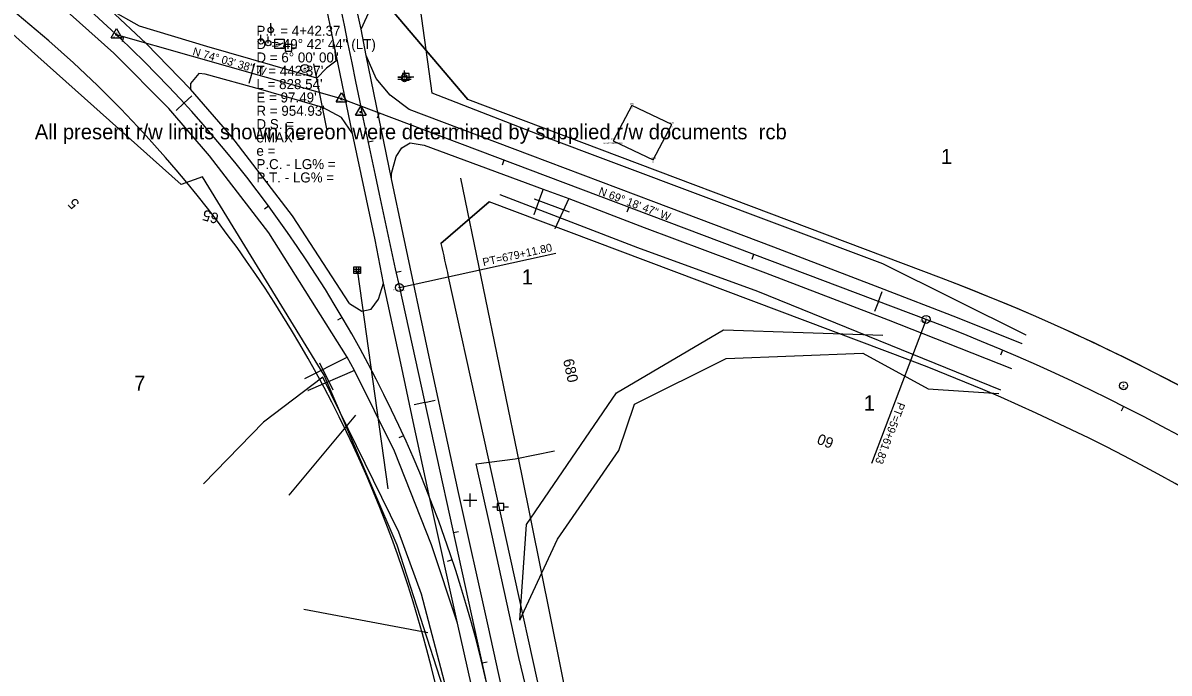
# Model space of a CAD drawing. Extents: x 2519952 to 2531965, y 848341 to 887632.
# Drawn here: x 2522518 to 2523377, y 863427 to 863914 of the extents above; entities that cross this region are included whole.
import ezdxf

# ---------------------------------------------------------------- set-up
doc = ezdxf.new("R2010")
doc.units = 0
for name, color, linetype in [('RD_EV_JW', 7, 'Continuous'), ('RD_EX_Bldg', 7, 'Continuous'), ('RD_EX_Bldg_txCode', 7, 'Continuous'), ('RD_EX_DR_Inlet', 7, 'Continuous'), ('RD_EX_DR_Pipe', 7, 'Continuous'), ('RD_EX_Driveway', 7, 'Continuous'), ('RD_EX_DV_Prop', 7, 'Continuous'), ('RD_EX_DV_TX_Prop', 7, 'Continuous'), ('RD_EX_H2O', 7, 'Continuous'), ('RD_EX_Misc', 7, 'Continuous'), ('RD_EX_Road', 7, 'Continuous'), ('RD_EX_RW', 7, 'Continuous'), ('RD_EX_RW_TX', 7, 'Continuous'), ('RD_EX_UT', 7, 'Continuous'), ('RD_EX_VEG', 7, 'Continuous'), ('RD_HC_Cl', 7, 'Continuous'), ('RD_HC_Data', 7, 'Continuous'), ('RD_HC_Data_Tic', 7, 'Continuous'), ('RD_HC_Survey_txCode', 7, 'Continuous'), ('RD_HC_TX_Sta50', 7, 'Continuous'), ('RD_HC_txCode', 7, 'Continuous'), ('RD_SMD_Locator', 7, 'Continuous')]:
    doc.layers.add(name, color=color, linetype=linetype)

msp = doc.modelspace()

# ---------------------------------------------------------------- linework, layer by layer
at = {"layer": 'RD_EV_JW'}
for points in [[(2522920.53, 863055.57), (2522899.94, 863070.57), (2522889.91, 863131.31), (2522869.96, 863279.01), (2522857.45, 863332.73), (2522834.29, 863420.16), (2522816.96, 863485.78), (2522800.18, 863532.41), (2522743.02, 863648.45), (2522698.57, 863614.71), (2522653.78, 863568.51)], [(2522920.53, 863055.57), (2522967.57, 863070.75), (2522981.27, 863100.18), (2522962.21, 863158.09), (2522937.17, 863227.1), (2522907.56, 863365.86), (2522890.04, 863438.41), (2522868, 863538.84), (2522858.07, 863583.56), (2522887.19, 863587.35), (2522916.66, 863593.29)]]:
    msp.add_lwpolyline(points, dxfattribs=at)
at = {"layer": 'RD_EX_Bldg'}
msp.add_lwpolyline([(2522960.63, 863825.67), (2522990.59, 863811.41), (2523004.65, 863837.91), (2522974.69, 863852.17), (2522960.63, 863825.67)], dxfattribs=at)
at = {"layer": 'RD_EX_DR_Inlet'}
for p, q in [((2522766.4, 863729.6), (2522771.4, 863729.6)), ((2522766.4, 863727.9), (2522771.4, 863727.9)), ((2522768.1, 863731.3), (2522768.1, 863726.3)), ((2522769.8, 863731.3), (2522769.8, 863726.3))]:
    msp.add_line(p, q, dxfattribs=at)
msp.add_lwpolyline([(2522766.4, 863726.3), (2522766.4, 863731.3), (2522771.4, 863731.3), (2522771.4, 863726.3)], close=True, dxfattribs=at)
at = {"layer": 'RD_EX_DR_Pipe'}
for p, q in [((2522746.04, 863834.81), (2522736.32, 863883.57)), ((2522901.44, 863782.38), (2522927.64, 863772.55)), ((2522769.09, 863727.62), (2522791.79, 863564.8)), ((2522740.58, 863659.27), (2522750.51, 863639.06))]:
    msp.add_line(p, q, dxfattribs=at)
at = {"layer": 'RD_EX_Driveway'}
for p, q in [((2522927.39, 863782.47), (2522917, 863759.7)), ((2522729.74, 863647.45), (2522761.34, 863663.47)), ((2522766.87, 863653.47), (2522732.02, 863638.61))]:
    msp.add_line(p, q, dxfattribs=at)
for points in [[(2522771.84, 863909.39), (2522780.26, 863928.09), (2522784.52, 863933.36), (2522789.39, 863937.12), (2522787.58, 863945.49), (2522773.78, 863941.61), (2522764.08, 863945.89)], [(2522908.2, 863789.47), (2522906.31, 863784.3), (2522901.18, 863770.21)]]:
    msp.add_lwpolyline(points, dxfattribs=at)
at = {"layer": 'RD_EX_DV_Prop'}
for p, q in [((2522795.07, 863923.37), (2522851.83, 863856.71)), ((2523206.85, 863722.65), (2522851.83, 863856.71)), ((2522831.66, 863748.88), (2522867.9, 863780.1)), ((2523183.54, 863660.91), (2522867.9, 863780.1)), ((2522837.15, 863723.81), (2522952.89, 863198.2))]:
    msp.add_line(p, q, dxfattribs=at)
for centre, radius, start, end in [((2521934.11, 863209.88), 917.43, 12.4185, 62.13074), ((2533991.57, 866180.03), 11421.66, 192.289656, 192.418432), ((2522660.36, 862275.4), 1546.99, 54.66603, 69.31315), ((2522660.36, 862275.4), 1480.99, 51.25287, 69.31316)]:
    msp.add_arc(centre, radius, start, end, dxfattribs=at)
at = {"layer": 'RD_EX_H2O'}
for p, q in [((2522767.7, 863619.95), (2522717.61, 863559.92)), ((2522821.78, 863456.92), (2522728.84, 863474.4))]:
    msp.add_line(p, q, dxfattribs=at)
for points in [[(2522890.89, 863466.28), (2522895.7, 863538.1), (2522943.3, 863607.52), (2522943.3, 863607.52), (2522963.12, 863636.85), (2523043.42, 863684.11), (2523162.85, 863679.99)], [(2522964.9, 863593.49), (2522976.59, 863628.23), (2523045.48, 863662.45), (2523147.88, 863666.63), (2523196.8, 863639.73), (2523249.79, 863636.38)], [(2522890.89, 863466.28), (2522918.88, 863526.99), (2522964.9, 863593.49)]]:
    msp.add_lwpolyline(points, dxfattribs=at)
at = {"layer": 'RD_EX_Misc'}
for p, q in [((2522853.61, 863551.25), (2522853.61, 863561.25)), ((2522848.61, 863556.25), (2522858.61, 863556.25))]:
    msp.add_line(p, q, dxfattribs=at)
at = {"layer": 'RD_EX_Road'}
for p, q in [((2522751.62, 863897.74), (2522733.8, 863986.7)), ((2522771.84, 863909.39), (2522764.08, 863945.89)), ((2522775.53, 863889.71), (2522771.84, 863909.39)), ((2522765.47, 863831.25), (2522751.62, 863897.74)), ((2522794.55, 863797.32), (2522775.53, 863889.71)), ((2522782.26, 863751.41), (2522765.47, 863831.25)), ((2522803.25, 863755.71), (2522794.55, 863797.32)), ((2522788.71, 863719.11), (2522782.26, 863751.41)), ((2522823.6, 863660.17), (2522803.25, 863755.71)), ((2522802.24, 863655.48), (2522788.71, 863719.11)), ((2522810.8, 863615.27), (2522802.24, 863655.48)), ((2522844.82, 863562.13), (2522823.6, 863660.17)), ((2522823.44, 863557.42), (2522810.8, 863615.27)), ((2522866.96, 863462.16), (2522844.82, 863562.13)), ((2522844.01, 863463.99), (2522823.44, 863557.42)), ((2522868.85, 863354.59), (2522844.01, 863463.99)), ((2522889.9, 863359.05), (2522866.96, 863462.16))]:
    msp.add_line(p, q, dxfattribs=at)
for points in [[(2522763.04, 863703.86), (2522720.49, 863769.52), (2522675.03, 863828.86), (2522643.95, 863864.61), (2522610.71, 863898.7), (2522583.42, 863924.34), (2522509.44, 863984.38), (2522472.42, 864010.52), (2522415.92, 864045.51), (2522371.01, 864070.62), (2522290.91, 864113.54), (2522244.18, 864138.18), (2522226.69, 864147.69), (2522181.87, 864171.51), (2522090.17, 864219.94), (2521993.25, 864270.98), (2521902.37, 864319.21), (2521807.87, 864368.77), (2521688.87, 864431.57), (2521616.84, 864469.6)], [(2522844.01, 863463.99), (2522824.66, 863522.83), (2522796.94, 863592.94), (2522766.87, 863653.47), (2522761.34, 863663.47), (2522702.61, 863756.77), (2522658.29, 863814.42), (2522627.65, 863849.99), (2522586.57, 863891.52), (2522541.94, 863931.24), (2522493.64, 863968.79), (2522452.52, 863997.49), (2522405.51, 864026.29), (2522355.83, 864053.86), (2522273.16, 864098.34), (2522258.63, 864105.97), (2522193.74, 864140.48), (2522082.28, 864199.49), (2521982.82, 864251.83), (2521904.9, 864293.41), (2521796.98, 864350.06), (2521702.09, 864400.08), (2521605.1, 864451.65)], [(2522751.62, 863897.74), (2522752.96, 863885.44), (2522745.86, 863880.13), (2522738.59, 863872.63), (2522656.24, 863896.54), (2522605.74, 863911.84), (2522583.42, 863924.34)], [(2523267.26, 863673.64), (2523218.83, 863693.06), (2523160.56, 863715.49), (2523081.05, 863745.9), (2522991.3, 863779.99), (2522898.4, 863815.04), (2522807.94, 863849.21), (2522793.48, 863860.12), (2522783.12, 863872.54), (2522775.53, 863889.71)], [(2522765.47, 863831.25), (2522757.24, 863843.34), (2522743.24, 863850.85), (2522696.64, 863864.37), (2522654.92, 863875.67), (2522650.21, 863876.13), (2522644.07, 863868.64), (2522643.95, 863864.61)], [(2522794.55, 863797.32), (2522794.72, 863801.3), (2522798.11, 863813.99), (2522802.45, 863820.6), (2522808.47, 863824.21), (2522819.15, 863822.57), (2522889.98, 863796.22), (2522908.2, 863789.47), (2522927.39, 863782.47), (2522983.89, 863760.78), (2523074.92, 863726.74), (2523166.83, 863691.55), (2523210.54, 863674.18), (2523259.23, 863655.13)], [(2522763.04, 863703.86), (2522772.35, 863697.96), (2522779.42, 863699.44), (2522784.95, 863706.96), (2522788.71, 863719.11)]]:
    msp.add_lwpolyline(points, dxfattribs=at)
at = {"layer": 'RD_EX_RW'}
for p, q in [((2522851.83, 863856.71), (2522795.07, 863923.37)), ((2523206.85, 863722.65), (2522851.83, 863856.71)), ((2522867.9, 863780.1), (2522831.66, 863748.88)), ((2523183.54, 863660.91), (2522867.9, 863780.1)), ((2522837.15, 863723.81), (2522952.89, 863198.19))]:
    msp.add_line(p, q, dxfattribs=at)
for centre, radius, start, end in [((2521934.11, 863209.88), 917.43, 12.41849, 62.13076), ((2533991.33, 866179.98), 11421.41, 192.289704, 192.418483), ((2522660.36, 862275.4), 1546.99, 51.25288, 69.31313), ((2522660.36, 862275.4), 1480.99, 51.25288, 69.31313)]:
    msp.add_arc(centre, radius, start, end, dxfattribs=at)
at = {"layer": 'RD_EX_UT'}
for p, q in [((2522704.06, 863908.91), (2522704.06, 863913.91)), ((2522696.77, 863900.37), (2522696.77, 863905.37)), ((2522702.2, 863899.03), (2522702.2, 863904.03)), ((2522719.88, 863898.03), (2522714.88, 863898.03)), ((2522714.88, 863898.03), (2522714.88, 863893.03)), ((2522719.88, 863893.03), (2522719.88, 863898.03)), ((2522711.45, 863895.46), (2522714.92, 863895.46)), ((2522714.88, 863893.03), (2522719.88, 863893.03)), ((2522719.81, 863895.46), (2522723.45, 863895.46)), ((2522804.19, 863878.59), (2522804.19, 863875.52)), ((2522799.26, 863873.54), (2522802.19, 863873.54)), ((2522799.37, 863872.1), (2522802.3, 863872.1)), ((2522799.45, 863873.63), (2522802.92, 863873.63)), ((2522807.88, 863876.19), (2522802.88, 863876.19)), ((2522802.88, 863876.19), (2522802.88, 863871.19)), ((2522802.88, 863871.19), (2522807.88, 863871.19)), ((2522804.3, 863877.15), (2522804.3, 863874.09)), ((2522806.19, 863873.54), (2522809.26, 863873.54)), ((2522806.3, 863872.1), (2522809.37, 863872.1)), ((2522807.81, 863873.63), (2522811.45, 863873.63)), ((2522807.88, 863871.19), (2522807.88, 863876.19)), ((2522878.7, 863553.79), (2522873.7, 863553.79)), ((2522873.7, 863553.79), (2522873.7, 863548.79)), ((2522878.7, 863548.79), (2522878.7, 863553.79)), ((2522870.27, 863551.23), (2522873.74, 863551.23)), ((2522873.7, 863548.79), (2522878.7, 863548.79)), ((2522878.63, 863551.23), (2522882.27, 863551.23))]:
    msp.add_line(p, q, dxfattribs=at)
msp.add_lwpolyline([(2522707.27, 863894.93), (2522707.27, 863901.93), (2522714.27, 863901.93), (2522714.27, 863894.93)], close=True, dxfattribs=at)
msp.add_lwpolyline([(2522708.17, 863897.92), (2522710.59, 863898.82), (2522710.25, 863897.58), (2522713.29, 863899.17)], dxfattribs=at)
for centre in [(2522704.06, 863908.91), (2522696.77, 863900.37), (2522702.2, 863899.03), (2522804.19, 863873.52), (2522804.3, 863872.09)]:
    msp.add_circle(centre, 2, dxfattribs=at)
at = {"layer": 'RD_EX_VEG'}
for points in [[(2522825.14, 863861.51), (2522810.56, 863966.4), (2522773.64, 864197.63), (2522752.31, 864294.16), (2522742.25, 864388.13), (2522724.04, 864484.42), (2522705.33, 864582.97), (2522691.6, 864679.36), (2522674.36, 864776.12), (2522660.93, 864871.67), (2522646.11, 864969.46), (2522630.15, 865068.16), (2522615.45, 865155.18)], [(2522798.87, 863522.57), (2522744.05, 863650.12), (2522652.87, 863798.84), (2522637.07, 863792.95), (2522463.94, 863947.66), (2522384.78, 863996.45), (2522233.81, 864089.72), (2522203.22, 864043.87)], [(2523270.29, 863679.97), (2523162.85, 863733.64), (2523085.67, 863762.44), (2522904.13, 863830.78), (2522825.14, 863861.51)], [(2522984.98, 863128.55), (2522971.23, 863183.64), (2522892.38, 863575.76), (2522846.47, 863797.78)], [(2522875.69, 863785.61), (2522978.87, 863745.72), (2523068.99, 863713.08), (2523251.04, 863639.11)], [(2522909.17, 863079.6), (2522892.22, 863170.11), (2522850.98, 863360.49), (2522798.87, 863522.57)]]:
    msp.add_lwpolyline(points, dxfattribs=at)
at = {"layer": 'RD_HC_Cl'}
for p, q in [((2522757.1, 863857.21), (2522588.47, 863905.37)), ((2523195.2, 863691.78), (2522757.1, 863857.21)), ((2522800.52, 863715.74), (2523357.12, 861188.1))]:
    msp.add_line(p, q, dxfattribs=at)
for centre, radius, start, end in [((2533991.33, 866179.98), 11458.91, 187.825051, 192.418483), ((2521934.11, 863209.88), 954.93, 12.41849, 62.13076), ((2522660.36, 862275.4), 1513.99, 51.25288, 69.31313)]:
    msp.add_arc(centre, radius, start, end, dxfattribs=at)
at = {"layer": 'RD_HC_Data'}
for p, q in [((2522584.49, 863903.08), (2522588.47, 863909.96)), ((2522588.47, 863909.96), (2522592.44, 863903.08)), ((2522584.49, 863903.08), (2522592.44, 863903.08)), ((2522753.13, 863854.92), (2522757.1, 863861.79)), ((2522757.1, 863861.79), (2522761.07, 863854.92)), ((2522753.13, 863854.92), (2522761.07, 863854.92)), ((2522767.59, 863844.97), (2522771.56, 863851.85)), ((2522767.59, 863844.97), (2522775.53, 863844.97)), ((2522771.56, 863851.85), (2522775.53, 863844.97)), ((2522800.52, 863715.74), (2522917.84, 863741.57)), ((2523195.2, 863691.78), (2523154.41, 863583.76))]:
    msp.add_line(p, q, dxfattribs=at)
for centre, radius in [((2522588.47, 863905.37), 0.529), ((2522729.65, 863880.04), 3), ((2522729.65, 863880.04), 0.282), ((2522757.1, 863857.21), 0.529), ((2522771.56, 863847.26), 0.529), ((2522800.52, 863715.74), 3), ((2522800.52, 863715.74), 0.282), ((2523195.2, 863691.78), 3), ((2523195.2, 863691.78), 0.282), ((2523343.22, 863642.12), 3), ((2523343.22, 863642.12), 0.282)]:
    msp.add_circle(centre, radius, dxfattribs=at)
at = {"layer": 'RD_HC_Data_Tic'}
for p, q in [((2522593.75, 863903.86), (2522592.65, 863900.02)), ((2522689.9, 863876.4), (2522692.1, 863884.09)), ((2522689.9, 863876.4), (2522687.71, 863868.71)), ((2522639.07, 863854.02), (2522633.17, 863848.62)), ((2522639.07, 863854.02), (2522644.98, 863859.41)), ((2522785.27, 863846.57), (2522783.86, 863842.83)), ((2522777.02, 863825.04), (2522780.93, 863825.86)), ((2522878.83, 863811.24), (2522877.41, 863807.5)), ((2522702.54, 863776.8), (2522699.32, 863774.42)), ((2522972.38, 863775.92), (2522970.97, 863772.17)), ((2523065.93, 863740.59), (2523064.52, 863736.85)), ((2522797.99, 863727.26), (2522801.9, 863728.12)), ((2523159.48, 863705.26), (2523162.31, 863712.75)), ((2523159.48, 863705.26), (2523156.66, 863697.78)), ((2522757.59, 863693.37), (2522754.14, 863691.35)), ((2523252.58, 863668.76), (2523251.01, 863665.08)), ((2522819.49, 863629.6), (2522811.68, 863627.88)), ((2522819.49, 863629.6), (2522827.31, 863631.32)), ((2523343.25, 863626.64), (2523341.45, 863623.07)), ((2522803.62, 863604.64), (2522799.98, 863602.99)), ((2522841, 863531.94), (2522844.9, 863532.8)), ((2522840.12, 863511.59), (2522836.33, 863510.33)), ((2522862.5, 863434.28), (2522866.41, 863435.14))]:
    msp.add_line(p, q, dxfattribs=at)
at = {"layer": 'RD_SMD_Locator'}
for centre in [(2522588.47, 863905.37), (2522605.74, 863911.84), (2522771.84, 863909.39), (2522771.84, 863909.39), (2522610.71, 863898.7), (2522656.24, 863896.54), (2522751.62, 863897.74), (2522751.62, 863897.74), (2522586.57, 863891.52), (2522775.53, 863889.71), (2522775.53, 863889.71), (2522729.65, 863880.04), (2522736.32, 863883.57), (2522745.86, 863880.13), (2522752.96, 863885.44), (2522650.21, 863876.13), (2522654.92, 863875.67), (2522738.59, 863872.63), (2522783.12, 863872.54), (2522643.95, 863864.61), (2522643.95, 863864.61), (2522644.07, 863868.64), (2522696.64, 863864.37), (2522825.14, 863861.51), (2522825.14, 863861.51), (2522757.1, 863857.21), (2522793.48, 863860.12), (2522627.65, 863849.99), (2522743.24, 863850.85), (2522771.56, 863847.26), (2522807.94, 863849.21), (2522974.69, 863852.17), (2522757.24, 863843.34), (2523004.65, 863837.91), (2522675.03, 863828.86), (2522746.04, 863834.81), (2522765.47, 863831.25), (2522765.47, 863831.25), (2522904.13, 863830.78), (2522802.45, 863820.6), (2522808.47, 863824.21), (2522819.15, 863822.57), (2522960.63, 863825.67), (2522960.63, 863825.67), (2522658.29, 863814.42), (2522798.11, 863813.99), (2522898.4, 863815.04), (2522990.59, 863811.41), (2522794.72, 863801.3), (2522637.07, 863792.95), (2522652.87, 863798.84), (2522794.55, 863797.32), (2522794.55, 863797.32), (2522846.47, 863797.78), (2522889.98, 863796.22), (2522875.69, 863785.61), (2522906.31, 863784.3), (2522908.2, 863789.47), (2522908.2, 863789.47), (2522901.44, 863782.38), (2522927.39, 863782.47), (2522927.39, 863782.47), (2522991.3, 863779.99), (2522720.49, 863769.52), (2522901.18, 863770.21), (2522927.64, 863772.55), (2522917, 863759.7), (2522983.89, 863760.78), (2523085.67, 863762.44), (2522702.61, 863756.77), (2522782.26, 863751.41), (2522803.25, 863755.71), (2522978.87, 863745.72), (2523081.05, 863745.9), (2523162.85, 863733.64), (2522769.09, 863727.62), (2523074.92, 863726.74), (2522788.71, 863719.11), (2522788.71, 863719.11), (2522800.52, 863715.74), (2523160.56, 863715.49), (2522784.95, 863706.96), (2523068.99, 863713.08), (2522763.04, 863703.86), (2522763.04, 863703.86), (2522779.42, 863699.44), (2522772.35, 863697.96), (2523166.83, 863691.55), (2523195.2, 863691.78), (2523218.83, 863693.06), (2523043.42, 863684.11), (2523162.85, 863679.99), (2523210.54, 863674.18), (2523267.26, 863673.64), (2523270.29, 863679.97), (2523147.88, 863666.63), (2522740.58, 863659.27), (2522761.34, 863663.47), (2522761.34, 863663.47), (2522802.24, 863655.48), (2522823.6, 863660.17), (2523045.48, 863662.45), (2523259.23, 863655.13), (2522729.74, 863647.45), (2522743.02, 863648.45), (2522744.05, 863650.12), (2522766.87, 863653.47), (2522766.87, 863653.47), (2522732.02, 863638.61), (2522750.51, 863639.06), (2523196.8, 863639.73), (2523251.04, 863639.11), (2523343.22, 863642.12), (2522963.12, 863636.85), (2523249.79, 863636.38), (2522976.59, 863628.23), (2522698.57, 863614.71), (2522767.7, 863619.95), (2522810.8, 863615.27), (2522943.3, 863607.52), (2522943.3, 863607.52), (2522796.94, 863592.94), (2522887.19, 863587.35), (2522916.66, 863593.29), (2522964.9, 863593.49), (2522964.9, 863593.49), (2522858.07, 863583.56), (2522892.38, 863575.76), (2522653.78, 863568.51), (2522791.79, 863564.8), (2522844.82, 863562.13), (2522717.61, 863559.92), (2522823.44, 863557.42), (2522868, 863538.84), (2522895.7, 863538.1), (2522800.18, 863532.41), (2522918.88, 863526.99), (2522798.87, 863522.57), (2522798.87, 863522.57), (2522824.66, 863522.83), (2522816.96, 863485.78), (2522728.84, 863474.4), (2522890.89, 863466.28), (2522890.89, 863466.28), (2522844.01, 863463.99), (2522844.01, 863463.99), (2522866.96, 863462.16), (2522821.78, 863456.92), (2522890.04, 863438.41)]:
    msp.add_circle(centre, 0.001, dxfattribs=at)

# ---------------------------------------------------------------- texts
at = {"layer": 'RD_EX_Bldg_txCode'}
for s, p in [('1483', (2522973.35, 863853.17)), ('B', (2522974.39, 863850.17)), ('1482', (2523003.31, 863838.91)), ('B', (2523004.35, 863835.91)), ('1480', (2522959.25, 863826.67)), ('1484', (2522959.29, 863826.67)), ('BA BARNABANDONED', (2522953.17, 863823.67)), ('BB', (2522959.85, 863823.67)), ('1481', (2522989.53, 863812.41)), ('B', (2522990.29, 863809.41))]:
    msp.add_text(s, height=1, dxfattribs=at).set_placement(p)
at = {"layer": 'RD_EX_DV_TX_Prop'}
for s, p in [('1', (2523206.37, 863808.43)), ('1', (2522892.13, 863718.03)), ('7', (2522601.78, 863638.41)), ('1', (2523148.46, 863623.52))]:
    msp.add_text(s, height=11.32, dxfattribs=at).set_placement(p)
at = {"layer": 'RD_EX_RW_TX'}
msp.add_text('All present r/w limits shown hereon were determined by supplied r/w documents  rcb', height=11.3167, dxfattribs=at).set_placement((2522527.28, 863826.9))
at = {"layer": 'RD_EX_UT'}
for p in [(2522803.52, 863872.47), (2522803.63, 863871.04)]:
    msp.add_text('T', height=2, dxfattribs=at).set_placement(p)
at = {"layer": 'RD_HC_Data'}
for s, rotation, p in [('PT=679+11.80', 12.41848, (2522863.57, 863731.67)), ('PT=59+61.83', 249.31313, (2523174.11, 863630.26))]:
    msp.add_text(s, height=6, rotation=rotation, dxfattribs=at).set_placement(p)
at = {"layer": 'RD_HC_Survey_txCode'}
for s, p in [('P.I. = 4+42.37', (2522693.36, 863904.54)), ('D', (2522693.36, 863894.54)), ('    = 49%%d 42\' 44" (LT)', (2522693.36, 863894.54)), ('D = 6%%d 00\' 00"', (2522693.36, 863884.54)), ("T = 442.37'", (2522693.36, 863874.54)), ("L = 828.54'", (2522693.36, 863864.54)), ("E = 97.49'", (2522693.36, 863854.54)), ("R = 954.93'", (2522693.36, 863844.54)), ('D.S. = ', (2522693.36, 863834.54)), ('eMAX = ', (2522693.36, 863824.54)), ('e = ', (2522693.36, 863814.54)), ('P.C. - LG% = ', (2522693.36, 863804.54)), ('P.T. - LG% = ', (2522693.36, 863794.54))]:
    msp.add_text(s, height=7.5, dxfattribs=at).set_placement(p)
for s, rotation, p in [('N 74%%d 03\' 38" W', 344.06047, (2522645.13, 863890.23)), ('N 69%%d 18\' 47" W', 339.31313, (2522949.33, 863785.69))]:
    msp.add_text(s, height=6, rotation=rotation, dxfattribs=at).set_placement(p)
at = {"layer": 'RD_HC_TX_Sta50'}
for s, rotation, p in [('5', 132.41852, (2522561.25, 863779.08)), ('65', 164.06047, (2522665.78, 863770.97)), ('680', 282.41848, (2522923.09, 863661.36)), ('60', 159.31313, (2523126.75, 863602.18))]:
    msp.add_text(s, height=8, rotation=rotation, dxfattribs=at).set_placement(p)
at = {"layer": 'RD_HC_txCode'}
for s, p in [('PI 66+05.50', (2522584.28, 863903.37)), ('26', (2522587.71, 863906.37)), ('CP 7 MSC', (2522726.02, 863878.04)), ('7', (2522729.36, 863881.04)), ('PI 64+30.12', (2522753.26, 863855.21)), ('25', (2522756.37, 863858.21)), ('PI 4+42.37', (2522767.95, 863845.26)), ('17', (2522771.11, 863848.26)), ('13', (2522800.08, 863716.74)), ('PT 679+11.80', (2522795.87, 863713.74)), ('PT 59+61.83', (2523190.75, 863689.78)), ('23', (2523194.46, 863692.78)), ('CP 9 MSC', (2523339.59, 863640.12)), ('9', (2523342.94, 863643.12))]:
    msp.add_text(s, height=1, dxfattribs=at).set_placement(p)

doc.saveas('drawing.dxf')
